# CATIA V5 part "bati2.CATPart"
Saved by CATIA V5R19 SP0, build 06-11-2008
Part number: bati
Bounding box of the stored display mesh (mm): x -16 to -10, y -2.997 to 41.872, z -14.867 to 33.963
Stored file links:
  C:\Users\rcousturie\Desktop\EU_thinkMotion\iao\IAO_MMS_Groupe1\glenerrant\glenerrant\Nouveau dossier\bati2.CATPart
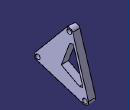
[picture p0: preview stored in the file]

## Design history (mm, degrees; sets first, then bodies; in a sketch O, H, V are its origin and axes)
Set1
  Point1: (0, 0, 0)
  Point2: (0, 26, 31)
  Point3: (0, 39, -12)
  Plane1: type Offset, RefPlane yz-plane, Offset 10, reversed
Body1 (main body)
  Line1 to Line4: stored without definition
  Sketch1 on Plane1, origin (-10, 0, 0), H (0, 1, 0), V (0, 0, 1)
    circle A1 centre (26, 31) radius 2
    point P1 (26, 31)
    circle A2 centre (39, -12) radius 2
    point P2 (39, -12)
    circle A3 centre (0, 0) radius 2
    point P3 (0, 0)
    arc A4 centre (39, -12) radius 3 from (38.1177, -14.8673) to (41.8716, -11.1318) ccw
    point P4 (39, -12)
    arc A5 centre (0, 0) radius 3 from (-2.2986, 1.9278) to (-0.8823, -2.8673) ccw
    point P5 (0, 0)
    arc A6 centre (26, 31) radius 3 from (28.8716, 31.8682) to (23.7014, 32.9278) ccw
    point P6 (26, 31)
    reference projected point E1 (0, 0) from Point1
    reference projected point E2 (26, 31) from Point2
    reference projected point E3 (39, -12) from Point3
    reference projected point E4 (0, 0) from Point1
    reference projected point E5 (26, 31) from Point2
    reference projected point E6 (39, -12) from Point3
    line L1 (-2.2986, 1.9278) -> (23.7014, 32.9278)
    line L2 (-0.8823, -2.8673) -> (38.1177, -14.8673)
    line L3 (28.8716, 31.8682) -> (41.8716, -11.1318)
    reference projected line E7 (39, -12) -> (0, 0) from Line3
    reference projected line E8 (0, 0) -> (26, 31) from Line4
    line L4 (19.4644, 4.0048) -> (34.4811, -3.9639)
    point P14 (34.4811, -3.9639)
    line L5 (34.4811, -3.9639) -> (37.3527, -3.0957)
    point P15 (34.4811, -3.9639)
    line L6 (29.2723, 23.6317) -> (26.4007, 22.7635)
    line L7 (19.4644, 4.0048) -> (26.4007, 22.7635)
    line L8 (29.2723, 23.6317) -> (37.3527, -3.0957)
    reference projected point E9 (26, 31) from Point2
    reference projected point E10 (39, -12) from Point3
    radius A4 = 3
    radius A6 = 3
    radius A1 = 2
    radius A2 = 2
    radius A5 = 3
    radius A3 = 2
    distance L8 L3 = 2
    length L6 = 3
    length L5 = 3
    distance E9 L6 = 8
    distance E10 L5 = 9
    length L7 = 20
    length L4 = 17
    coincidence: P5 E1, P6 E2, P4 E3, E4 P3, E5 P1, P2 E6, P14 P15
    tangency: L1 A6, A6 L3, L2 A5, A4 L3
    parallelism: L2 E7, L1 E8, L6 L5
    perpendicularity: L5 L8
  Pad1: profile Sketch1, direction (-1, 0, 0), length 6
